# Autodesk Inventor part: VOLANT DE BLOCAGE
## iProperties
Created: 2004-11
Part Number: VOLANT DE BLOCAGE
Document SubType Name: Modeling
Designer: Bruno
Manufacturer: Standard
Standards Organization: Custom
Author: Bruno
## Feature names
1. Base1
